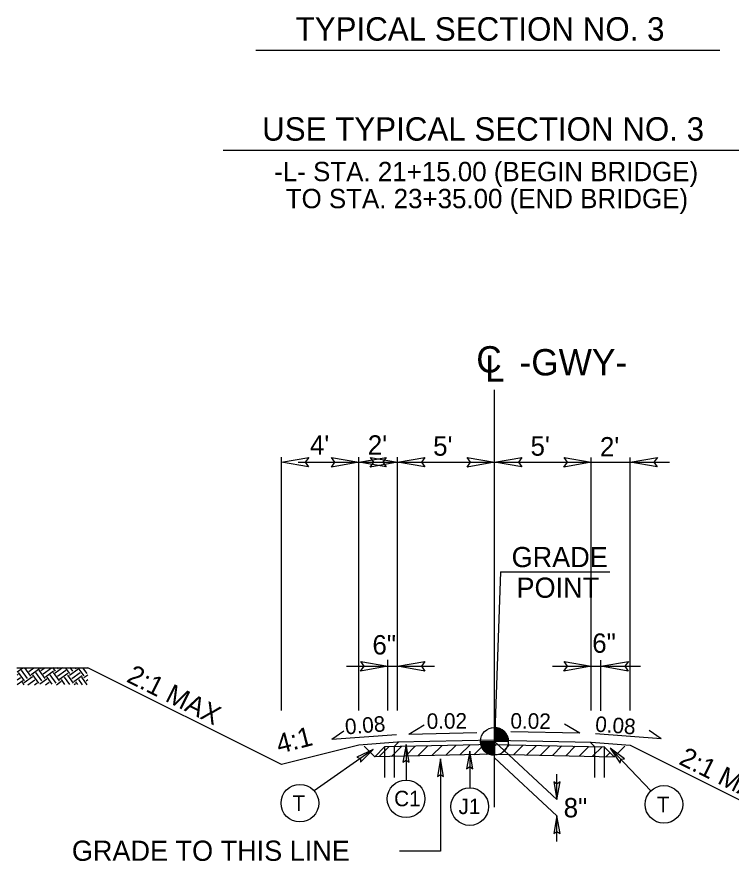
# Model space of a CAD drawing. Extents: x 1184121 to 1184397, y 1246506 to 1246661.
# Drawn here: x 1184281.29 to 1184318.17, y 1246571.8 to 1246615.42 of the extents above; entities that cross this region are included whole.
import ezdxf

# ---------------------------------------------------------------- set-up
doc = ezdxf.new("R2010")
doc.units = 0
doc.layers.add('Scratch_Level_1', color=7, linetype='Continuous')
doc.layers.add('Sheet Data Field CELL', color=7, linetype='Continuous')

msp = doc.modelspace()

# ---------------------------------------------------------------- linework, layer by layer
at = {"layer": 'Scratch_Level_1'}
for p, q in [((1184300.279, 1246577.716), (1184300.279, 1246576.113)), ((1184300.779, 1246577.716), (1184300.779, 1246576.113)), ((1184311.119, 1246577.716), (1184311.119, 1246576.113)), ((1184311.619, 1246577.716), (1184311.619, 1246576.113))]:
    msp.add_line(p, q, dxfattribs=at)
at = {"layer": 'Sheet Data Field CELL'}
for p, q in [((1184293.624, 1246613.695), (1184317.578, 1246613.695)), ((1184291.942, 1246608.527), (1184319.717, 1246608.527)), ((1184305.949, 1246574.593), (1184305.949, 1246596.157)), ((1184294.949, 1246579.577), (1184294.949, 1246592.671)), ((1184298.949, 1246579.577), (1184298.949, 1246592.671)), ((1184300.949, 1246579.577), (1184300.949, 1246592.671)), ((1184310.949, 1246579.577), (1184310.949, 1246592.655)), ((1184312.949, 1246579.577), (1184312.949, 1246592.655)), ((1184295.819, 1246592.407), (1184305.949, 1246592.407)), ((1184305.949, 1246592.407), (1184314.985, 1246592.407)), ((1184306.253, 1246586.738), (1184305.949, 1246577.986)), ((1184306.253, 1246586.738), (1184311.913, 1246586.738)), ((1184300.449, 1246579.587), (1184300.449, 1246582.197)), ((1184311.449, 1246579.567), (1184311.449, 1246582.177)), ((1184281.294, 1246581.791), (1184284.948, 1246581.791)), ((1184281.294, 1246581.791), (1184284.948, 1246581.791)), ((1184281.308, 1246581.579), (1184281.604, 1246581.791)), ((1184281.308, 1246581.579), (1184281.604, 1246581.791)), ((1184281.848, 1246581.234), (1184281.539, 1246581.663)), ((1184281.848, 1246581.234), (1184281.539, 1246581.663)), ((1184282.009, 1246581.349), (1184281.7, 1246581.779)), ((1184282.009, 1246581.349), (1184281.7, 1246581.779)), ((1184281.793, 1246581.764), (1184281.831, 1246581.792)), ((1184281.793, 1246581.764), (1184281.831, 1246581.792)), ((1184281.908, 1246581.603), (1184282.173, 1246581.793)), ((1184281.908, 1246581.603), (1184282.173, 1246581.793)), ((1184282.024, 1246581.442), (1184282.454, 1246581.751)), ((1184282.024, 1246581.442), (1184282.454, 1246581.751)), ((1184282.748, 1246581.229), (1184282.439, 1246581.658)), ((1184282.748, 1246581.229), (1184282.439, 1246581.658)), ((1184282.546, 1246581.735), (1184282.504, 1246581.794)), ((1184282.546, 1246581.735), (1184282.504, 1246581.794)), ((1184282.531, 1246581.643), (1184282.742, 1246581.795)), ((1184282.531, 1246581.643), (1184282.742, 1246581.795)), ((1184282.647, 1246581.482), (1184283.077, 1246581.791)), ((1184282.647, 1246581.482), (1184283.077, 1246581.791)), ((1184282.763, 1246581.321), (1184283.192, 1246581.63)), ((1184282.763, 1246581.321), (1184283.192, 1246581.63)), ((1184283.285, 1246581.615), (1184283.154, 1246581.796)), ((1184283.285, 1246581.615), (1184283.154, 1246581.796)), ((1184283.27, 1246581.522), (1184283.652, 1246581.797)), ((1184283.27, 1246581.522), (1184283.652, 1246581.797)), ((1184283.385, 1246581.361), (1184283.815, 1246581.67)), ((1184283.385, 1246581.361), (1184283.815, 1246581.67)), ((1184283.446, 1246581.73), (1184283.398, 1246581.796)), ((1184283.446, 1246581.73), (1184283.398, 1246581.796)), ((1184284.023, 1246581.494), (1184283.81, 1246581.791)), ((1184284.023, 1246581.494), (1184283.81, 1246581.791)), ((1184284.008, 1246581.401), (1184284.438, 1246581.71)), ((1184284.008, 1246581.401), (1184284.438, 1246581.71)), ((1184284.184, 1246581.609), (1184284.048, 1246581.798)), ((1184284.184, 1246581.609), (1184284.048, 1246581.798)), ((1184284.345, 1246581.725), (1184284.298, 1246581.791)), ((1184284.345, 1246581.725), (1184284.298, 1246581.791)), ((1184284.761, 1246581.373), (1184284.461, 1246581.791)), ((1184284.761, 1246581.373), (1184284.461, 1246581.791)), ((1184284.923, 1246581.489), (1184284.706, 1246581.791)), ((1184284.923, 1246581.489), (1184284.706, 1246581.791)), ((1184294.949, 1246576.79), (1184284.948, 1246581.791)), ((1184298.317, 1246581.865), (1184302.861, 1246581.865)), ((1184308.94, 1246581.865), (1184313.485, 1246581.865)), ((1184281.308, 1246581.416), (1184281.363, 1246581.455)), ((1184281.308, 1246581.416), (1184281.363, 1246581.455)), ((1184281.308, 1246581.172), (1184281.479, 1246581.294)), ((1184281.308, 1246581.172), (1184281.479, 1246581.294)), ((1184281.687, 1246581.118), (1184281.378, 1246581.548)), ((1184281.687, 1246581.118), (1184281.378, 1246581.548)), ((1184281.672, 1246581.026), (1184282.101, 1246581.334)), ((1184281.672, 1246581.026), (1184282.101, 1246581.334)), ((1184281.86, 1246580.916), (1184282.217, 1246581.173)), ((1184281.86, 1246580.916), (1184282.217, 1246581.173)), ((1184282.425, 1246580.997), (1184282.117, 1246581.427)), ((1184282.425, 1246580.997), (1184282.117, 1246581.427)), ((1184282.586, 1246581.113), (1184282.278, 1246581.542)), ((1184282.586, 1246581.113), (1184282.278, 1246581.542)), ((1184282.487, 1246580.96), (1184282.84, 1246581.213)), ((1184282.487, 1246580.96), (1184282.84, 1246581.213)), ((1184283.113, 1246580.947), (1184282.855, 1246581.306)), ((1184283.113, 1246580.947), (1184282.855, 1246581.306)), ((1184283.325, 1246580.992), (1184283.016, 1246581.422)), ((1184283.325, 1246580.992), (1184283.016, 1246581.422)), ((1184283.486, 1246581.108), (1184283.177, 1246581.537)), ((1184283.486, 1246581.108), (1184283.177, 1246581.537)), ((1184283.501, 1246581.2), (1184283.931, 1246581.509)), ((1184283.501, 1246581.2), (1184283.931, 1246581.509)), ((1184283.774, 1246580.934), (1184283.593, 1246581.185)), ((1184283.774, 1246580.934), (1184283.593, 1246581.185)), ((1184284.022, 1246580.929), (1184283.755, 1246581.301)), ((1184284.022, 1246580.929), (1184283.755, 1246581.301)), ((1184284.224, 1246580.987), (1184283.916, 1246581.416)), ((1184284.224, 1246580.987), (1184283.916, 1246581.416)), ((1184284.124, 1246581.24), (1184284.553, 1246581.549)), ((1184284.124, 1246581.24), (1184284.553, 1246581.549)), ((1184284.239, 1246581.079), (1184284.669, 1246581.388)), ((1184284.239, 1246581.079), (1184284.669, 1246581.388)), ((1184284.683, 1246580.916), (1184284.493, 1246581.18)), ((1184284.683, 1246580.916), (1184284.493, 1246581.18)), ((1184284.93, 1246580.911), (1184284.654, 1246581.296)), ((1184284.93, 1246580.911), (1184284.654, 1246581.296)), ((1184284.746, 1246581.28), (1184284.948, 1246581.426)), ((1184284.746, 1246581.28), (1184284.948, 1246581.426)), ((1184284.862, 1246581.119), (1184284.948, 1246581.181)), ((1184284.862, 1246581.119), (1184284.948, 1246581.181)), ((1184281.308, 1246580.927), (1184281.595, 1246581.133)), ((1184281.308, 1246580.927), (1184281.595, 1246581.133)), ((1184281.669, 1246580.916), (1184281.579, 1246581.041)), ((1184281.669, 1246580.916), (1184281.579, 1246581.041)), ((1184282.2, 1246580.916), (1184282.333, 1246581.012)), ((1184282.2, 1246580.916), (1184282.333, 1246581.012)), ((1184282.766, 1246580.916), (1184282.956, 1246581.052)), ((1184282.766, 1246580.916), (1184282.956, 1246581.052)), ((1184283.333, 1246580.916), (1184283.578, 1246581.093)), ((1184283.333, 1246580.916), (1184283.578, 1246581.093)), ((1184284.251, 1246580.925), (1184284.317, 1246580.972)), ((1184284.251, 1246580.925), (1184284.317, 1246580.972)), ((1184284.435, 1246580.921), (1184284.332, 1246581.064)), ((1184284.435, 1246580.921), (1184284.332, 1246581.064)), ((1184301.536, 1246578.367), (1184302.319, 1246578.84)), ((1184305.949, 1246577.986), (1184305.949, 1246578.702)), ((1184310.356, 1246578.411), (1184309.573, 1246578.884)), ((1184314.55, 1246578.115), (1184313.929, 1246578.543)), ((1184297.556, 1246578.095), (1184298.177, 1246578.523)), ((1184297.556, 1246578.095), (1184300.887, 1246578.345)), ((1184301.536, 1246578.367), (1184305.033, 1246578.437)), ((1184310.356, 1246578.411), (1184306.8, 1246578.482)), ((1184314.55, 1246578.115), (1184311.157, 1246578.37)), ((1184298.949, 1246577.79), (1184294.949, 1246576.79)), ((1184300.949, 1246577.95), (1184298.949, 1246577.79)), ((1184299.217, 1246577.747), (1184299.769, 1246577.195)), ((1184300.279, 1246577.706), (1184299.769, 1246577.195)), ((1184299.99, 1246577.2), (1184300.501, 1246577.71)), ((1184305.952, 1246577.819), (1184300.279, 1246577.706)), ((1184300.632, 1246577.213), (1184301.142, 1246577.723)), ((1184301.02, 1246577.956), (1184300.779, 1246577.716)), ((1184305.949, 1246578.05), (1184300.949, 1246577.95)), ((1184301.354, 1246577.227), (1184301.864, 1246577.737)), ((1184301.387, 1246577.819), (1184301.387, 1246575.991)), ((1184301.995, 1246577.24), (1184302.506, 1246577.75)), ((1184302.717, 1246577.254), (1184303.227, 1246577.765)), ((1184303.439, 1246577.269), (1184303.949, 1246577.779)), ((1184304.16, 1246577.283), (1184304.67, 1246577.794)), ((1184304.882, 1246577.298), (1184305.392, 1246577.808)), ((1184305.233, 1246577.986), (1184305.949, 1246577.986)), ((1184305.523, 1246577.31), (1184306.03, 1246577.817)), ((1184305.946, 1246577.819), (1184311.619, 1246577.706)), ((1184305.948, 1246577.27), (1184305.949, 1246577.986)), ((1184305.949, 1246577.986), (1184305.948, 1246577.27)), ((1184305.949, 1246578.05), (1184310.949, 1246577.95)), ((1184306.665, 1246577.986), (1184305.949, 1246577.986)), ((1184305.949, 1246577.986), (1184309.177, 1246574.986)), ((1184306.241, 1246577.313), (1184306.731, 1246577.803)), ((1184306.934, 1246577.299), (1184307.424, 1246577.79)), ((1184307.627, 1246577.285), (1184308.117, 1246577.776)), ((1184308.32, 1246577.272), (1184308.811, 1246577.762)), ((1184308.937, 1246577.259), (1184309.427, 1246577.75)), ((1184309.63, 1246577.245), (1184310.121, 1246577.736)), ((1184310.324, 1246577.231), (1184310.814, 1246577.722)), ((1184310.883, 1246577.951), (1184311.119, 1246577.716)), ((1184310.949, 1246577.95), (1184312.949, 1246577.79)), ((1184311.017, 1246577.218), (1184311.507, 1246577.708)), ((1184311.619, 1246577.706), (1184312.13, 1246577.195)), ((1184312.681, 1246577.747), (1184312.13, 1246577.195)), ((1184312.949, 1246577.79), (1184323.077, 1246572.726)), ((1184299.683, 1246577.567), (1184296.646, 1246575.423)), ((1184305.949, 1246577.319), (1184299.769, 1246577.195)), ((1184304.674, 1246577.481), (1184304.674, 1246575.587)), ((1184305.949, 1246577.319), (1184312.13, 1246577.195)), ((1184311.71, 1246577.204), (1184311.916, 1246577.409)), ((1184311.931, 1246577.639), (1184314.025, 1246575.433)), ((1184303.165, 1246577.079), (1184303.165, 1246572.32)), ((1184305.949, 1246577.134), (1184309.177, 1246574.134)), ((1184309.177, 1246574.986), (1184309.177, 1246576.291)), ((1184309.177, 1246572.818), (1184309.177, 1246574.134)), ((1184303.165, 1246572.32), (1184301.047, 1246572.32))]:
    msp.add_line(p, q, dxfattribs=at)
for points in [[(1184296.355, 1246592.165), (1184294.949, 1246592.407), (1184296.363, 1246592.657), (1184296.183, 1246592.407)], [(1184297.543, 1246592.649), (1184298.949, 1246592.407), (1184297.535, 1246592.157), (1184297.715, 1246592.407)], [(1184300.355, 1246592.165), (1184298.949, 1246592.407), (1184300.363, 1246592.657), (1184300.183, 1246592.407)], [(1184299.543, 1246592.649), (1184300.949, 1246592.407), (1184299.535, 1246592.157), (1184299.715, 1246592.407)], [(1184302.355, 1246592.165), (1184300.949, 1246592.407), (1184302.363, 1246592.657), (1184302.183, 1246592.407)], [(1184304.543, 1246592.649), (1184305.949, 1246592.407), (1184304.535, 1246592.157), (1184304.715, 1246592.407)], [(1184307.355, 1246592.165), (1184305.949, 1246592.407), (1184307.363, 1246592.657), (1184307.183, 1246592.407)], [(1184309.543, 1246592.649), (1184310.949, 1246592.407), (1184309.535, 1246592.157), (1184309.715, 1246592.407)], [(1184314.355, 1246592.165), (1184312.949, 1246592.407), (1184314.363, 1246592.657), (1184314.183, 1246592.407)], [(1184299.043, 1246582.107), (1184300.449, 1246581.865), (1184299.035, 1246581.615), (1184299.215, 1246581.865)], [(1184302.355, 1246581.622), (1184300.949, 1246581.865), (1184302.363, 1246582.115), (1184302.183, 1246581.865)], [(1184309.543, 1246582.107), (1184310.949, 1246581.865), (1184309.535, 1246581.615), (1184309.715, 1246581.865)], [(1184312.855, 1246581.622), (1184311.449, 1246581.865), (1184312.863, 1246582.115), (1184312.683, 1246581.865)], [(1184301.544, 1246576.91), (1184301.387, 1246577.819), (1184301.225, 1246576.905), (1184301.387, 1246577.021)], [(1184299.031, 1246576.915), (1184299.683, 1246577.567), (1184298.843, 1246577.172), (1184299.031, 1246577.107)], [(1184304.831, 1246576.571), (1184304.674, 1246577.481), (1184304.512, 1246576.566), (1184304.674, 1246576.682)], [(1184312.671, 1246577.087), (1184311.931, 1246577.639), (1184312.444, 1246576.864), (1184312.481, 1246577.06)], [(1184303.321, 1246576.169), (1184303.165, 1246577.079), (1184303.003, 1246576.164), (1184303.165, 1246576.28)], [(1184309.019, 1246575.895), (1184309.177, 1246574.986), (1184309.338, 1246575.901), (1184309.176, 1246575.784)], [(1184309.333, 1246573.225), (1184309.177, 1246574.134), (1184309.015, 1246573.22), (1184309.177, 1246573.336)]]:
    msp.add_lwpolyline(points, close=True, dxfattribs=at)
for points in [[(1184305.956, 1246578.702), (1184305.956, 1246578.702), (1184305.956, 1246577.986)], [(1184305.97, 1246578.702), (1184305.97, 1246577.986)], [(1184305.984, 1246578.7), (1184305.984, 1246577.986)], [(1184305.998, 1246578.7), (1184305.998, 1246577.986)], [(1184306.013, 1246578.699), (1184306.013, 1246577.986)], [(1184306.027, 1246578.697), (1184306.027, 1246577.986)], [(1184306.041, 1246578.696), (1184306.041, 1246577.986)], [(1184306.056, 1246578.694), (1184306.056, 1246577.986)], [(1184306.07, 1246578.692), (1184306.07, 1246577.986)], [(1184306.084, 1246578.689), (1184306.084, 1246577.986)], [(1184306.099, 1246578.686), (1184306.099, 1246577.986)], [(1184306.113, 1246578.683), (1184306.113, 1246577.986)], [(1184306.127, 1246578.68), (1184306.127, 1246577.986)], [(1184306.142, 1246578.675), (1184306.142, 1246577.986)], [(1184306.156, 1246578.672), (1184306.156, 1246577.986)], [(1184306.17, 1246578.667), (1184306.17, 1246577.986)], [(1184306.185, 1246578.662), (1184306.185, 1246577.986)], [(1184306.199, 1246578.657), (1184306.199, 1246577.986)], [(1184306.213, 1246578.651), (1184306.213, 1246577.986)], [(1184306.228, 1246578.645), (1184306.228, 1246577.986)], [(1184306.242, 1246578.638), (1184306.242, 1246577.986)], [(1184306.256, 1246578.632), (1184306.256, 1246577.986)], [(1184306.271, 1246578.626), (1184306.271, 1246577.986)], [(1184306.285, 1246578.618), (1184306.285, 1246577.986)], [(1184306.299, 1246578.61), (1184306.299, 1246577.986)], [(1184306.314, 1246578.602), (1184306.314, 1246577.986)], [(1184306.328, 1246578.594), (1184306.328, 1246577.986)], [(1184306.342, 1246578.584), (1184306.342, 1246577.986)], [(1184306.357, 1246578.575), (1184306.357, 1246577.986)], [(1184306.371, 1246578.564), (1184306.371, 1246577.986)], [(1184306.385, 1246578.554), (1184306.385, 1246577.986)], [(1184306.4, 1246578.543), (1184306.4, 1246577.986)], [(1184306.414, 1246578.53), (1184306.414, 1246577.986)], [(1184306.428, 1246578.517), (1184306.428, 1246577.986)], [(1184306.442, 1246578.505), (1184306.442, 1246577.986)], [(1184306.457, 1246578.49), (1184306.457, 1246577.986)], [(1184306.471, 1246578.476), (1184306.471, 1246577.986)], [(1184306.485, 1246578.46), (1184306.485, 1246577.986)], [(1184306.5, 1246578.443), (1184306.5, 1246577.986)], [(1184306.514, 1246578.425), (1184306.514, 1246577.986)], [(1184306.528, 1246578.406), (1184306.528, 1246577.986)], [(1184306.543, 1246578.385), (1184306.543, 1246577.986)], [(1184306.557, 1246578.363), (1184306.557, 1246577.986)], [(1184306.571, 1246578.339), (1184306.571, 1246577.986)], [(1184306.586, 1246578.314), (1184306.586, 1246577.986)], [(1184306.6, 1246578.283), (1184306.6, 1246577.986)], [(1184306.614, 1246578.25), (1184306.614, 1246577.986)], [(1184306.629, 1246578.21), (1184306.629, 1246577.986)], [(1184306.643, 1246578.161), (1184306.643, 1246577.986)], [(1184305.236, 1246577.986), (1184305.236, 1246577.908)], [(1184305.25, 1246577.986), (1184305.25, 1246577.823)], [(1184305.265, 1246577.986), (1184305.265, 1246577.773)], [(1184305.279, 1246577.986), (1184305.279, 1246577.73)], [(1184305.293, 1246577.986), (1184305.293, 1246577.696)], [(1184305.308, 1246577.986), (1184305.308, 1246577.666)], [(1184305.322, 1246577.986), (1184305.322, 1246577.639)], [(1184305.336, 1246577.986), (1184305.336, 1246577.613)], [(1184305.351, 1246577.986), (1184305.351, 1246577.591)], [(1184305.365, 1246577.986), (1184305.365, 1246577.57)], [(1184305.379, 1246577.986), (1184305.379, 1246577.551)], [(1184305.394, 1246577.986), (1184305.394, 1246577.534)], [(1184305.408, 1246577.986), (1184305.408, 1246577.516)], [(1184305.422, 1246577.986), (1184305.422, 1246577.5)], [(1184305.437, 1246577.986), (1184305.437, 1246577.485)], [(1184305.451, 1246577.986), (1184305.451, 1246577.47)], [(1184305.465, 1246577.986), (1184305.465, 1246577.457)], [(1184305.48, 1246577.986), (1184305.48, 1246577.445)], [(1184305.494, 1246577.986), (1184305.494, 1246577.432)], [(1184305.508, 1246577.986), (1184305.508, 1246577.421)], [(1184305.523, 1246577.986), (1184305.523, 1246577.41)], [(1184305.537, 1246577.986), (1184305.537, 1246577.4)], [(1184305.551, 1246577.986), (1184305.551, 1246577.391)], [(1184305.566, 1246577.986), (1184305.566, 1246577.381)], [(1184305.58, 1246577.986), (1184305.58, 1246577.372)], [(1184305.594, 1246577.986), (1184305.594, 1246577.364)], [(1184305.609, 1246577.986), (1184305.609, 1246577.356)], [(1184305.623, 1246577.986), (1184305.623, 1246577.348)], [(1184305.637, 1246577.986), (1184305.637, 1246577.341)], [(1184305.652, 1246577.986), (1184305.652, 1246577.335)], [(1184305.666, 1246577.986), (1184305.666, 1246577.329)], [(1184305.68, 1246577.986), (1184305.68, 1246577.322)], [(1184305.695, 1246577.986), (1184305.695, 1246577.316)], [(1184305.709, 1246577.986), (1184305.709, 1246577.311)], [(1184305.723, 1246577.986), (1184305.723, 1246577.306)], [(1184305.738, 1246577.986), (1184305.738, 1246577.301)], [(1184305.752, 1246577.986), (1184305.752, 1246577.298)], [(1184305.766, 1246577.986), (1184305.766, 1246577.294)], [(1184305.78, 1246577.986), (1184305.78, 1246577.29)], [(1184305.795, 1246577.986), (1184305.795, 1246577.287)], [(1184305.809, 1246577.986), (1184305.809, 1246577.284)], [(1184305.823, 1246577.986), (1184305.823, 1246577.281)], [(1184305.838, 1246577.986), (1184305.838, 1246577.279)], [(1184305.852, 1246577.986), (1184305.852, 1246577.276)], [(1184305.866, 1246577.986), (1184305.866, 1246577.274)], [(1184305.881, 1246577.986), (1184305.881, 1246577.273)], [(1184305.895, 1246577.986), (1184305.895, 1246577.271)], [(1184305.909, 1246577.986), (1184305.909, 1246577.271)], [(1184305.924, 1246577.986), (1184305.924, 1246577.27)], [(1184305.938, 1246577.986), (1184305.938, 1246577.27), (1184305.938, 1246577.27)], [(1184306.657, 1246578.088), (1184306.657, 1246577.986)]]:
    msp.add_lwpolyline(points, dxfattribs=at)
for centre, radius in [((1184305.948, 1246577.986), 0.716), ((1184301.386, 1246575.019), 0.972), ((1184295.905, 1246574.795), 0.972), ((1184304.672, 1246574.615), 0.972), ((1184314.7, 1246574.733), 0.972)]:
    msp.add_circle(centre, radius, dxfattribs=at)
for start, end in [(359.9905, 89.9905), (179.9905, 269.9905)]:
    msp.add_arc((1184305.948, 1246577.986), 0.716, start, end, dxfattribs=at)

# ---------------------------------------------------------------- texts
for s, height, p in [('TYPICAL SECTION NO. 3', 1.20892, (1184295.683, 1246614.192)), ('USE TYPICAL SECTION NO. 3', 1.20892, (1184293.954, 1246609.024)), ('C', 1.36, (1184305.012, 1246597.045)), ('-GWY-', 1.36, (1184307.244, 1246596.895)), ('GRADE', 1.044, (1184306.835, 1246586.988)), ('POINT', 1.044, (1184307.087, 1246585.406)), ('C1', 0.8, (1184300.769, 1246574.634)), ('J1', 0.8, (1184304.094, 1246574.229)), ('GRADE TO THIS LINE', 1.04396, (1184284.133, 1246571.815))]:
    msp.add_text(s, height=height, dxfattribs=at).set_placement(p)
for s, height, rotation, p in [('-L- STA. 21+15.00 (BEGIN BRIDGE) ', 1, 0.0002, (1184294.58, 1246606.928)), ('TO STA. 23+35.00 (END BRIDGE)', 1, 0.0002, (1184295.174, 1246605.533)), ('L', 1.361, 359.9469, (1184305.464, 1246596.58)), ("4'", 1, 359.9998, (1184296.422, 1246592.8)), ("2'", 1, 359.9998, (1184299.41, 1246592.8)), ("5'", 1, 359.9998, (1184302.784, 1246592.747)), ("5'", 1, 359.9998, (1184307.812, 1246592.747)), ("2'", 1, 359.9998, (1184311.393, 1246592.708)), ('6"', 1, 359.9998, (1184299.649, 1246582.478)), ('6"', 1, 359.9998, (1184310.997, 1246582.564)), ('2:1 MAX', 1, 333.4348, (1184286.898, 1246581.091)), ('0.02', 0.8, 0.5402, (1184302.454, 1246578.631)), ('0.02', 0.8, 359.4598, (1184306.772, 1246578.649)), ('0.08', 0.8, 4.5736, (1184298.265, 1246578.343)), ('0.08', 0.8, 355.7746, (1184311.13, 1246578.494)), ('4:1', 1, 14.371, (1184294.832, 1246577.342)), ('2:1 MAX.', 1, 333.4348, (1184315.411, 1246576.838)), ('T', 0.8, 359.9997, (1184295.525, 1246574.393)), ('8"', 1, 359.9998, (1184309.522, 1246574.061)), ('T', 0.8, 359.9997, (1184314.331, 1246574.325))]:
    msp.add_text(s, height=height, rotation=rotation, dxfattribs=at).set_placement(p)

doc.saveas('drawing.dxf')
